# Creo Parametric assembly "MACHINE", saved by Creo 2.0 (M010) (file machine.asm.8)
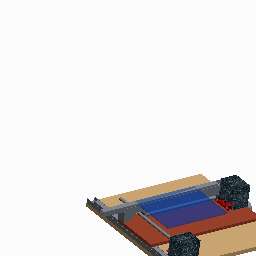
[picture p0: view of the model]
Units: Inch lbm Second (Pro/E Default); INCH, POUND, SECS

Created from: INLBS_ASM_DESIGN.ASM

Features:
  1. datum plane "ASM_RIGHT"
  2. datum plane "ASM_TOP"
  3. datum plane "ASM_FRONT"
  4. coordinate system
  5. component "BASE_BOARD"
  6. component "TOPBOARD"
  7. component "YMOTOR"
  8. component "MOTOR"
  9. component "PRT0001"
  10. component "SLIDE_TOP"
  11. component "THREADM6"
  12. component "SKATEBEARING"
  13. component "X_RAISER"
  14. component "PRT0001"
  15. component "SLIDE_TOP"
  16. component "MOTOR"
  17. component "YMOTOR"
  18. component "THREADM6"
  19. component "BED"

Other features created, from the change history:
  component "YMOTOR.PRT"
  component "BASE_BOARD.PRT"
  component "TOPBOARD.PRT"
  component "SKATEBEARING.PRT"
